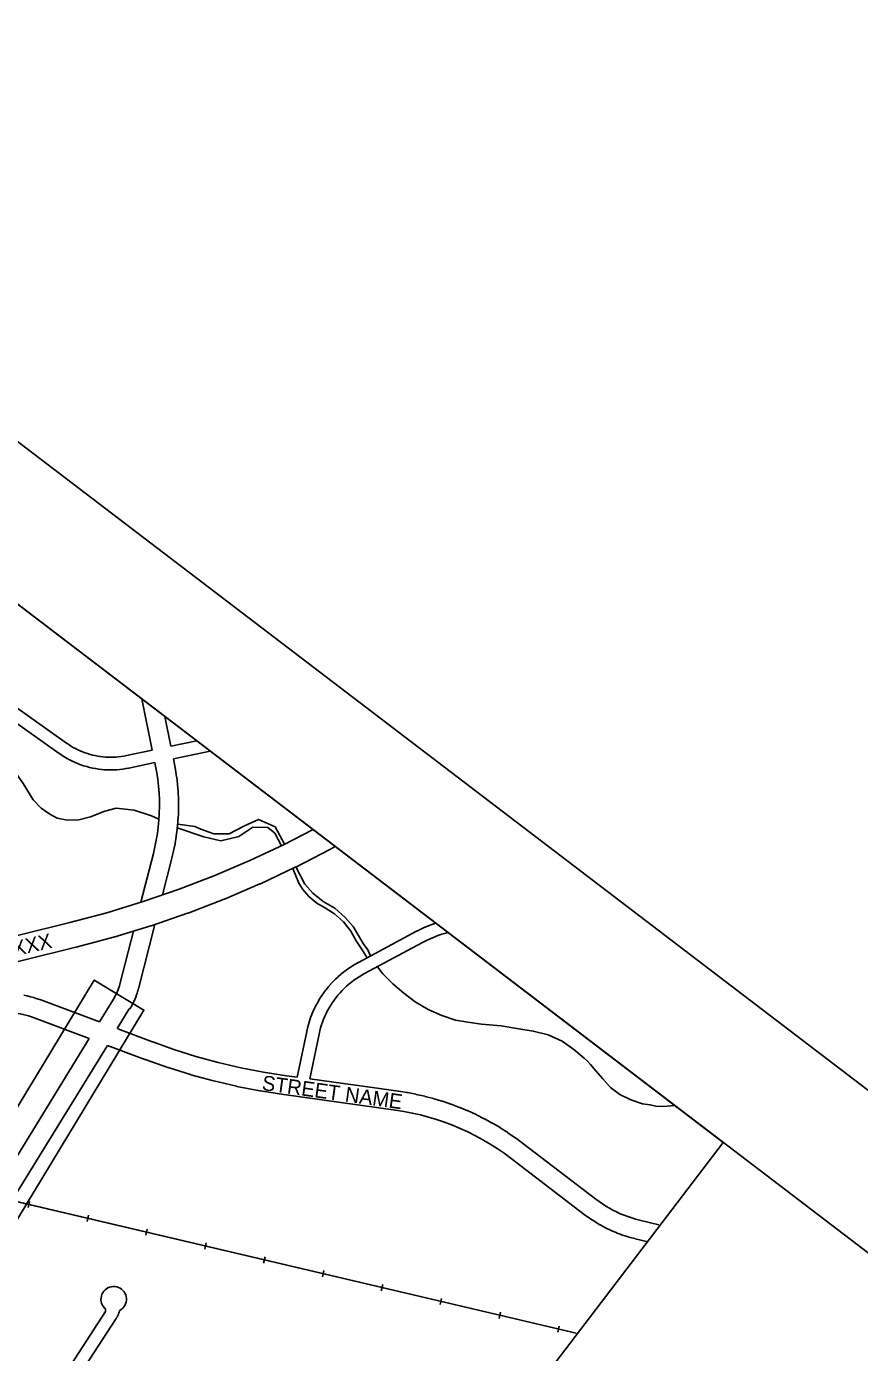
# Model space of a CAD drawing. Extents: x 599744 to 600217, y 4827560 to 4828065.
# Drawn here: x 600025.2 to 600064.4, y 4827997.7 to 4828060.2 of the extents above; entities that cross this region are included whole.
import ezdxf

# ---------------------------------------------------------------- set-up
doc = ezdxf.new("R2010")
doc.units = 0
for name, color, linetype in [('G-ANNO-KEYP', 7, 'Continuous'), ('G-TTLB-OTLN', 7, 'Continuous'), ('G-TTLB-OTLN-PB', 7, 'Continuous')]:
    doc.layers.add(name, color=color, linetype=linetype)

msp = doc.modelspace()

# ---------------------------------------------------------------- linework, layer by layer
at = {"layer": 'G-ANNO-KEYP'}
for p, q in [((600051.473, 4828011.574), (600051.624, 4828011.436)), ((600051.095, 4827998.607), (600022.395, 4828005.359)), ((600025.326, 4828004.824), (600025.257, 4828004.532)), ((600028.1, 4828004.171), (600028.032, 4828003.879)), ((600030.875, 4828003.518), (600030.806, 4828003.226)), ((600033.649, 4828002.866), (600033.58, 4828002.574)), ((600036.423, 4828002.213), (600036.355, 4828001.921)), ((600039.198, 4828001.56), (600039.129, 4828001.268)), ((600041.972, 4828000.908), (600041.903, 4828000.616)), ((600044.746, 4828000.255), (600044.678, 4827999.963)), ((600047.521, 4827999.602), (600047.452, 4827999.31)), ((600050.295, 4827998.95), (600050.226, 4827998.658))]:
    msp.add_line(p, q, dxfattribs=at)
for points in [[(600031.107, 4828026.096), (600029.887, 4828025.842), (600029.764, 4828025.818), (600029.642, 4828025.799), (600029.52, 4828025.784), (600029.397, 4828025.774), (600029.274, 4828025.768), (600029.151, 4828025.766), (600029.027, 4828025.768), (600028.904, 4828025.774), (600028.781, 4828025.784), (600028.659, 4828025.799), (600028.537, 4828025.818), (600028.416, 4828025.841), (600028.297, 4828025.868), (600028.177, 4828025.9), (600028.059, 4828025.935), (600027.942, 4828025.974), (600027.827, 4828026.018), (600027.713, 4828026.065), (600027.601, 4828026.116), (600027.491, 4828026.171), (600027.383, 4828026.23), (600027.276, 4828026.292), (600027.172, 4828026.358), (600027.068, 4828026.429), (600023.676, 4828028.831)], [(600031.107, 4828026.096), (600030.611, 4828028.515)], [(600031.227, 4828025.509), (600030.007, 4828025.255), (600030.002, 4828025.254), (600030.002, 4828025.254), (600029.871, 4828025.229), (600029.861, 4828025.227), (600029.861, 4828025.227), (600029.729, 4828025.207), (600029.72, 4828025.205), (600029.719, 4828025.205), (600029.587, 4828025.189), (600029.587, 4828025.189), (600029.587, 4828025.189), (600029.586, 4828025.189), (600029.586, 4828025.189), (600029.576, 4828025.188), (600029.443, 4828025.177), (600029.442, 4828025.177), (600029.433, 4828025.176), (600029.299, 4828025.169), (600029.298, 4828025.17), (600029.289, 4828025.169), (600029.156, 4828025.167), (600029.154, 4828025.167), (600029.145, 4828025.167), (600029.012, 4828025.169), (600029.01, 4828025.17), (600029.002, 4828025.169), (600028.868, 4828025.176), (600028.866, 4828025.177), (600028.858, 4828025.177), (600028.725, 4828025.188), (600028.723, 4828025.189), (600028.715, 4828025.189), (600028.583, 4828025.205), (600028.579, 4828025.207), (600028.572, 4828025.207), (600028.44, 4828025.227), (600028.437, 4828025.229), (600028.43, 4828025.229), (600028.299, 4828025.254), (600028.295, 4828025.256), (600028.289, 4828025.256), (600028.159, 4828025.285), (600028.155, 4828025.288), (600028.149, 4828025.288), (600028.02, 4828025.322), (600028.015, 4828025.324), (600028.01, 4828025.325), (600027.882, 4828025.363), (600027.877, 4828025.366), (600027.873, 4828025.366), (600027.746, 4828025.409), (600027.741, 4828025.412), (600027.736, 4828025.412), (600027.611, 4828025.459), (600027.606, 4828025.462), (600027.602, 4828025.463), (600027.479, 4828025.514), (600027.472, 4828025.518), (600027.469, 4828025.518), (600027.348, 4828025.573), (600027.341, 4828025.577), (600027.339, 4828025.578), (600027.219, 4828025.637), (600027.212, 4828025.642), (600027.21, 4828025.642), (600027.093, 4828025.706), (600027.086, 4828025.71), (600027.084, 4828025.711), (600026.969, 4828025.778), (600026.961, 4828025.783), (600026.96, 4828025.784), (600026.847, 4828025.855), (600026.839, 4828025.86), (600026.839, 4828025.861), (600026.728, 4828025.936), (600026.724, 4828025.939), (600026.724, 4828025.939), (600023.332, 4828028.341)], [(600031.423, 4828022.843), (600031.069, 4828022.999), (600030.258, 4828023.267), (600029.409, 4828023.358), (600028.876, 4828023.215), (600028.192, 4828022.961), (600027.646, 4828022.814), (600027.113, 4828022.802), (600026.619, 4828022.899), (600026.276, 4828023.086), (600025.874, 4828023.361), (600025.496, 4828023.753), (600025.019, 4828024.527), (600024.778, 4828024.893), (600024.478, 4828025.28), (600024.088, 4828025.705), (600023.545, 4828026.035), (600022.805, 4828026.349), (600021.978, 4828026.699), (600021.327, 4828027.074), (600020.789, 4828027.56), (600020.706, 4828027.738)], [(600031.699, 4828027.685), (600031.987, 4828026.279)], [(600033.209, 4828026.533), (600031.987, 4828026.279)], [(600032.108, 4828025.692), (600033.839, 4828026.053)], [(600030.572, 4828018.933), (600031.16, 4828021.23), (600031.235, 4828021.543), (600031.298, 4828021.856), (600031.35, 4828022.171), (600031.391, 4828022.486), (600031.421, 4828022.804), (600031.44, 4828023.122), (600031.447, 4828023.441), (600031.444, 4828023.76), (600031.43, 4828024.078), (600031.404, 4828024.396), (600031.367, 4828024.713), (600031.32, 4828025.028), (600031.261, 4828025.345), (600031.227, 4828025.509)], [(600032.108, 4828025.692), (600032.142, 4828025.522), (600032.144, 4828025.515), (600032.144, 4828025.515), (600032.205, 4828025.186), (600032.208, 4828025.171), (600032.208, 4828025.17), (600032.258, 4828024.84), (600032.26, 4828024.828), (600032.26, 4828024.824), (600032.298, 4828024.492), (600032.298, 4828024.492), (600032.3, 4828024.476), (600032.327, 4828024.143), (600032.326, 4828024.142), (600032.328, 4828024.127), (600032.343, 4828023.793), (600032.342, 4828023.791), (600032.343, 4828023.777), (600032.347, 4828023.443), (600032.346, 4828023.44), (600032.347, 4828023.427), (600032.339, 4828023.093), (600032.337, 4828023.09), (600032.338, 4828023.077), (600032.318, 4828022.743), (600032.317, 4828022.739), (600032.317, 4828022.727), (600032.285, 4828022.394), (600032.284, 4828022.39), (600032.284, 4828022.379), (600032.241, 4828022.047), (600032.239, 4828022.042), (600032.238, 4828022.032), (600032.184, 4828021.702), (600032.181, 4828021.696), (600032.181, 4828021.686), (600032.115, 4828021.358), (600032.112, 4828021.352), (600032.112, 4828021.343), (600032.034, 4828021.017), (600032.033, 4828021.014), (600032.032, 4828021.01), (600031.587, 4828019.27)], [(600005.072, 4828012.476), (600027.218, 4828017.966), (600028.959, 4828018.431), (600030.677, 4828018.956), (600032.375, 4828019.541), (600034.051, 4828020.187), (600035.703, 4828020.892), (600037.329, 4828021.656), (600038.687, 4828022.354)], [(600037.2, 4828021.595), (600036.879, 4828022.179), (600036.553, 4828022.452), (600035.854, 4828022.471), (600035.186, 4828022.029), (600034.346, 4828021.826), (600033.537, 4828022.011), (600032.289, 4828022.436)], [(600032.306, 4828022.607), (600033.117, 4828022.506), (600033.393, 4828022.372), (600034.008, 4828022.151), (600034.737, 4828022.156), (600035.429, 4828022.516), (600036.11, 4828022.832), (600036.908, 4828022.482), (600037.343, 4828021.663)], [(600039.735, 4828021.554), (600039.503, 4828021.425), (600039.492, 4828021.421), (600039.484, 4828021.415), (600037.868, 4828020.584), (600037.856, 4828020.58), (600037.848, 4828020.575), (600036.203, 4828019.802), (600036.19, 4828019.798), (600036.184, 4828019.793), (600034.512, 4828019.08), (600034.498, 4828019.076), (600034.492, 4828019.072), (600032.796, 4828018.418), (600032.781, 4828018.414), (600032.776, 4828018.411), (600031.058, 4828017.818), (600031.041, 4828017.815), (600031.037, 4828017.812), (600029.299, 4828017.281), (600029.282, 4828017.277), (600029.278, 4828017.275), (600027.522, 4828016.806), (600027.513, 4828016.804), (600027.512, 4828016.804), (600003.91, 4828010.952)], [(600037.727, 4828020.517), (600038.017, 4828019.82), (600038.2, 4828019.528), (600038.491, 4828019.203), (600038.872, 4828018.892), (600039.27, 4828018.653), (600039.695, 4828018.383), (600040.116, 4828018.007), (600040.462, 4828017.569), (600040.725, 4828017.112), (600040.997, 4828016.692), (600041.239, 4828016.312)], [(600041.396, 4828016.396), (600041.267, 4828016.691), (600041.054, 4828016.99), (600040.833, 4828017.368), (600040.578, 4828017.785), (600040.203, 4828018.212), (600039.706, 4828018.655), (600039.163, 4828018.968), (600038.675, 4828019.354), (600038.302, 4828019.788), (600037.881, 4828020.591)], [(600031.228, 4828017.873), (600030.452, 4828014.841), (600030.45, 4828014.838), (600030.45, 4828014.834), (600030.423, 4828014.737), (600030.42, 4828014.73), (600030.419, 4828014.723), (600030.389, 4828014.627), (600030.385, 4828014.619), (600030.385, 4828014.613), (600030.352, 4828014.518), (600030.347, 4828014.51), (600030.346, 4828014.504), (600030.31, 4828014.411), (600030.306, 4828014.402), (600030.305, 4828014.397), (600030.266, 4828014.304), (600030.26, 4828014.295), (600030.26, 4828014.291), (600030.217, 4828014.2), (600030.212, 4828014.19), (600030.211, 4828014.186), (600030.166, 4828014.097), (600030.159, 4828014.087), (600030.159, 4828014.084), (600030.111, 4828013.996), (600030.104, 4828013.985), (600030.103, 4828013.983), (600030.052, 4828013.897), (600030.048, 4828013.891)], [(600044.462, 4828017.948), (600044.375, 4828017.918), (600044.372, 4828017.916), (600044.365, 4828017.914), (600044.17, 4828017.839), (600044.167, 4828017.837), (600044.16, 4828017.835), (600043.968, 4828017.753), (600043.965, 4828017.751), (600043.959, 4828017.749), (600043.77, 4828017.66), (600043.766, 4828017.657), (600043.76, 4828017.655), (600043.574, 4828017.56), (600043.572, 4828017.559), (600043.57, 4828017.558), (600040.825, 4828016.091), (600040.823, 4828016.09)], [(600028.619, 4828013.284), (600029.28, 4828014.358), (600029.325, 4828014.435), (600029.366, 4828014.509), (600029.405, 4828014.585), (600029.441, 4828014.663), (600029.474, 4828014.741), (600029.504, 4828014.82), (600029.532, 4828014.901), (600029.558, 4828014.982), (600029.581, 4828015.068), (600030.22, 4828017.562)], [(600045.046, 4828017.503), (600044.953, 4828017.477), (600044.763, 4828017.419), (600044.576, 4828017.354), (600044.391, 4828017.282), (600044.208, 4828017.204), (600044.029, 4828017.12), (600043.85, 4828017.028), (600041.11, 4828015.564), (600040.979, 4828015.492), (600040.854, 4828015.416)], [(600040.823, 4828016.09), (600040.821, 4828016.089), (600040.683, 4828016.012), (600040.679, 4828016.009), (600040.674, 4828016.007), (600040.539, 4828015.926), (600040.535, 4828015.922), (600040.531, 4828015.92), (600040.399, 4828015.834), (600040.394, 4828015.83), (600040.39, 4828015.828), (600040.262, 4828015.738), (600040.257, 4828015.733), (600040.253, 4828015.732), (600040.128, 4828015.637), (600040.122, 4828015.632), (600040.119, 4828015.63), (600039.997, 4828015.531), (600039.992, 4828015.525), (600039.989, 4828015.524), (600039.871, 4828015.421), (600039.865, 4828015.415), (600039.863, 4828015.414), (600039.748, 4828015.306), (600039.742, 4828015.3), (600039.741, 4828015.299), (600039.63, 4828015.187), (600039.624, 4828015.18), (600039.623, 4828015.18), (600039.516, 4828015.064), (600039.509, 4828015.057), (600039.509, 4828015.057), (600039.406, 4828014.938), (600039.399, 4828014.93), (600039.399, 4828014.93), (600039.3, 4828014.807), (600039.297, 4828014.803), (600039.294, 4828014.799), (600039.2, 4828014.673), (600039.2, 4828014.673), (600039.193, 4828014.664), (600039.104, 4828014.535), (600039.103, 4828014.535), (600039.098, 4828014.527), (600039.012, 4828014.395), (600039.012, 4828014.393), (600039.007, 4828014.386), (600038.926, 4828014.251), (600038.926, 4828014.249), (600038.921, 4828014.241), (600038.845, 4828014.104), (600038.845, 4828014.101)], [(600040.854, 4828015.416), (600040.73, 4828015.335), (600040.611, 4828015.251), (600040.493, 4828015.162), (600040.379, 4828015.07), (600040.269, 4828014.973), (600040.162, 4828014.873), (600040.058, 4828014.769), (600039.958, 4828014.661), (600039.862, 4828014.55), (600039.77, 4828014.435), (600039.682, 4828014.318), (600039.598, 4828014.198), (600039.518, 4828014.074), (600039.443, 4828013.948), (600039.372, 4828013.819), (600039.306, 4828013.689), (600039.244, 4828013.555), (600039.187, 4828013.42), (600039.135, 4828013.282), (600039.088, 4828013.144), (600039.045, 4828013.003), (600039.008, 4828012.861), (600038.975, 4828012.715), (600038.532, 4828010.597)], [(600041.721, 4828015.891), (600041.98, 4828015.561), (600042.44, 4828015.081), (600042.96, 4828014.641), (600043.493, 4828014.226), (600044.109, 4828013.878), (600044.759, 4828013.597), (600045.405, 4828013.373), (600045.98, 4828013.278), (600046.621, 4828013.186), (600047.547, 4828013.102), (600048.287, 4828012.977), (600049.066, 4828012.858), (600049.77, 4828012.671), (600050.422, 4828012.38), (600050.976, 4828011.991), (600051.369, 4828011.664), (600051.473, 4828011.574)], [(600025.05, 4828014.547), (600025.2, 4828014.516), (600025.207, 4828014.513), (600025.215, 4828014.512), (600025.365, 4828014.476), (600025.372, 4828014.473), (600025.38, 4828014.472), (600025.528, 4828014.431), (600025.535, 4828014.427), (600025.542, 4828014.426), (600025.689, 4828014.38), (600025.697, 4828014.375), (600025.703, 4828014.375), (600025.848, 4828014.323), (600025.852, 4828014.321), (600025.856, 4828014.321), (600028.619, 4828013.284)], [(600038.845, 4828014.101), (600038.84, 4828014.094), (600038.769, 4828013.954), (600038.769, 4828013.951), (600038.765, 4828013.945), (600038.699, 4828013.802), (600038.698, 4828013.799), (600038.694, 4828013.792), (600038.633, 4828013.647), (600038.633, 4828013.644), (600038.63, 4828013.638), (600038.574, 4828013.491), (600038.573, 4828013.486), (600038.57, 4828013.481), (600038.519, 4828013.332), (600038.519, 4828013.327), (600038.516, 4828013.322), (600038.471, 4828013.171), (600038.47, 4828013.166), (600038.468, 4828013.161), (600038.428, 4828013.009), (600038.427, 4828013.003), (600038.425, 4828012.999), (600038.39, 4828012.845), (600038.39, 4828012.842), (600038.389, 4828012.84), (600037.937, 4828010.679)], [(600028.141, 4828012.503), (600025.543, 4828013.477), (600025.409, 4828013.525), (600025.278, 4828013.567), (600025.144, 4828013.604), (600025.009, 4828013.637), (600024.875, 4828013.665), (600024.738, 4828013.688), (600024.601, 4828013.707), (600024.463, 4828013.721), (600024.325, 4828013.731), (600024.187, 4828013.736), (600024.048, 4828013.736), (600023.91, 4828013.731), (600023.773, 4828013.722), (600023.635, 4828013.707), (600023.498, 4828013.689), (600023.361, 4828013.665)], [(600030.025, 4828013.906), (600030.025, 4828013.905), (600029.454, 4828012.977)], [(600029.477, 4828012.962), (600031.071, 4828012.364), (600031.071, 4828012.364), (600031.098, 4828012.354), (600031.127, 4828012.344), (600031.127, 4828012.344), (600031.127, 4828012.344), (600032.13, 4828011.989), (600033.169, 4828011.663), (600034.22, 4828011.376), (600035.281, 4828011.128), (600036.35, 4828010.919), (600037.431, 4828010.749), (600037.937, 4828010.679)], [(600023.749, 4828005.364), (600028.14, 4828012.504)], [(600028.997, 4828012.181), (600024.667, 4828005.141)], [(600054.398, 4828002.937), (600053.864, 4828003.067), (600053.861, 4828003.069), (600053.856, 4828003.069), (600053.656, 4828003.122), (600053.649, 4828003.125), (600053.641, 4828003.126), (600053.442, 4828003.185), (600053.434, 4828003.189), (600053.427, 4828003.19), (600053.23, 4828003.256), (600053.222, 4828003.261), (600053.216, 4828003.262), (600053.022, 4828003.335), (600053.013, 4828003.34), (600053.007, 4828003.34), (600052.816, 4828003.42), (600052.806, 4828003.426), (600052.801, 4828003.426), (600052.613, 4828003.513), (600052.603, 4828003.519), (600052.599, 4828003.519), (600052.413, 4828003.612), (600052.403, 4828003.619), (600052.399, 4828003.619), (600052.217, 4828003.718), (600052.206, 4828003.725), (600052.203, 4828003.726), (600052.025, 4828003.831), (600052.013, 4828003.839), (600052.011, 4828003.84), (600051.836, 4828003.951), (600051.825, 4828003.959), (600051.823, 4828003.96), (600051.652, 4828004.077), (600051.64, 4828004.086), (600051.64, 4828004.086), (600051.473, 4828004.209), (600051.467, 4828004.214), (600051.467, 4828004.214), (600048.021, 4828006.854), (600047.699, 4828007.092), (600047.371, 4828007.317), (600047.036, 4828007.531), (600046.694, 4828007.733), (600046.344, 4828007.923), (600045.989, 4828008.101), (600045.628, 4828008.267), (600045.261, 4828008.42), (600044.89, 4828008.561), (600044.513, 4828008.688), (600044.133, 4828008.803), (600043.749, 4828008.904), (600043.361, 4828008.992), (600042.971, 4828009.067), (600042.574, 4828009.129), (600037.303, 4828009.859), (600037.3, 4828009.86), (600037.295, 4828009.86), (600036.202, 4828010.032), (600036.196, 4828010.035), (600036.186, 4828010.035), (600035.1, 4828010.247), (600035.094, 4828010.25), (600035.084, 4828010.25), (600034.007, 4828010.502), (600034, 4828010.506), (600033.991, 4828010.506), (600032.924, 4828010.798), (600032.916, 4828010.802), (600032.908, 4828010.803), (600031.853, 4828011.133), (600031.844, 4828011.138), (600031.837, 4828011.138), (600030.826, 4828011.496), (600030.826, 4828011.496), (600030.794, 4828011.508), (600030.79, 4828011.51), (600030.787, 4828011.511), (600030.755, 4828011.522), (600030.755, 4828011.522), (600028.997, 4828012.182)], [(600051.624, 4828011.436), (600051.757, 4828011.285), (600052.018, 4828010.988), (600052.35, 4828010.602), (600052.703, 4828010.202), (600053.142, 4828009.867), (600053.661, 4828009.608), (600054.223, 4828009.429), (600054.568, 4828009.37), (600054.572, 4828009.376), (600054.844, 4828009.318), (600055.226, 4828009.304), (600055.703, 4828009.348), (600055.732, 4828009.351)], [(600038.532, 4828010.597), (600041.71, 4828010.157), (600041.71, 4828010.157), (600042.701, 4828010.019), (600042.704, 4828010.018), (600042.709, 4828010.018), (600043.117, 4828009.955), (600043.122, 4828009.952), (600043.132, 4828009.952), (600043.538, 4828009.874), (600043.544, 4828009.872), (600043.553, 4828009.871), (600043.955, 4828009.78), (600043.962, 4828009.776), (600043.97, 4828009.776), (600044.37, 4828009.67), (600044.377, 4828009.667), (600044.385, 4828009.666), (600044.78, 4828009.547), (600044.788, 4828009.543), (600044.795, 4828009.543), (600045.186, 4828009.41), (600045.194, 4828009.406), (600045.2, 4828009.405), (600045.587, 4828009.259), (600045.595, 4828009.254), (600045.601, 4828009.253), (600045.982, 4828009.094)], [(600045.982, 4828009.094), (600045.991, 4828009.088), (600045.996, 4828009.088), (600046.371, 4828008.916), (600046.381, 4828008.91), (600046.385, 4828008.909), (600046.755, 4828008.724), (600046.765, 4828008.717), (600046.768, 4828008.717), (600047.131, 4828008.519), (600047.142, 4828008.512), (600047.144, 4828008.512), (600047.5, 4828008.302), (600047.511, 4828008.294), (600047.513, 4828008.294), (600047.861, 4828008.072), (600047.873, 4828008.063), (600047.874, 4828008.063), (600048.214, 4828007.829), (600048.226, 4828007.82), (600048.227, 4828007.82), (600048.559, 4828007.575), (600048.565, 4828007.57), (600048.565, 4828007.57), (600052.011, 4828004.93), (600052.168, 4828004.814), (600052.326, 4828004.705), (600052.488, 4828004.602), (600052.654, 4828004.505), (600052.822, 4828004.413), (600052.994, 4828004.327), (600053.168, 4828004.247), (600053.346, 4828004.174), (600053.525, 4828004.106), (600053.707, 4828004.045), (600053.891, 4828003.99), (600054.081, 4828003.94), (600054.993, 4828003.718)], [(600051.095, 4827998.607), (600022.395, 4828005.359), (600022.332, 4828005.373), (600021.896, 4828005.471), (600021.46, 4828005.561), (600021.022, 4828005.643), (600020.585, 4828005.716), (600020.145, 4828005.782), (600019.704, 4828005.843), (600019.262, 4828005.893), (600018.819, 4828005.936), (600018.374, 4828005.971), (600017.929, 4828006), (600017.485, 4828006.019), (600017.041, 4828006.032), (600016.596, 4828006.037), (600016.15, 4828006.033), (600015.707, 4828006.022), (600015.26, 4828006.004), (600014.818, 4828005.977), (600014.372, 4828005.943), (600013.93, 4828005.9), (600013.487, 4828005.851)], [(600026.008, 4827995.17), (600028.908, 4827999.634), (600028.908, 4827999.753), (600028.847, 4827999.812), (600028.794, 4827999.879), (600028.752, 4827999.952), (600028.72, 4828000.031), (600028.7, 4828000.113), (600028.691, 4828000.197), (600028.695, 4828000.282), (600028.71, 4828000.365), (600028.737, 4828000.446), (600028.775, 4828000.522), (600028.824, 4828000.591), (600028.881, 4828000.653), (600028.947, 4828000.707), (600029.02, 4828000.75), (600029.098, 4828000.783), (600029.18, 4828000.805), (600029.264, 4828000.814), (600029.349, 4828000.812), (600029.433, 4828000.798), (600029.514, 4828000.772), (600029.59, 4828000.735), (600029.66, 4828000.688), (600029.723, 4828000.631), (600029.778, 4828000.566), (600029.822, 4828000.494), (600029.856, 4828000.416), (600029.879, 4828000.335), (600029.89, 4828000.251), (600029.889, 4828000.166), (600029.876, 4828000.082), (600029.851, 4828000.001), (600029.816, 4827999.924), (600029.769, 4827999.853), (600029.714, 4827999.789), (600029.649, 4827999.734), (600029.578, 4827999.688), (600029.548, 4827999.625), (600029.547, 4827999.619), (600029.54, 4827999.593), (600029.538, 4827999.588), (600029.537, 4827999.582), (600029.529, 4827999.556), (600029.526, 4827999.551), (600029.526, 4827999.546), (600029.516, 4827999.52), (600029.513, 4827999.514), (600029.513, 4827999.51), (600029.503, 4827999.484), (600029.499, 4827999.478), (600029.498, 4827999.474), (600029.487, 4827999.449), (600029.483, 4827999.442), (600029.483, 4827999.439), (600029.471, 4827999.414), (600029.467, 4827999.407), (600029.466, 4827999.405), (600029.453, 4827999.38), (600029.448, 4827999.373), (600029.448, 4827999.371), (600029.434, 4827999.347), (600029.429, 4827999.339), (600029.429, 4827999.338), (600029.414, 4827999.314), (600029.412, 4827999.31), (600029.411, 4827999.31), (600026.486, 4827994.807)]]:
    msp.add_lwpolyline(points, dxfattribs=at)
msp.add_lwpolyline([(600010.535, 4827985.796), (600028.374, 4828015.258), (600030.714, 4828013.841), (600012.874, 4827984.379)], close=True, dxfattribs=at)
msp.add_lwpolyline([(600010.535, 4827985.796), (600028.374, 4828015.258), (600030.714, 4828013.841), (600012.874, 4827984.379)], close=True, dxfattribs=at)
at = {"layer": 'G-TTLB-OTLN'}
msp.add_line((599997.478, 4828053.792), (600211.005, 4827890.894), dxfattribs=at)
msp.add_lwpolyline([(599983.747, 4827984.522), (600022.202, 4828034.93), (600058.02, 4828007.605), (600019.565, 4827957.197)], close=True, dxfattribs=at)
at = {"layer": 'G-TTLB-OTLN-PB'}
msp.add_lwpolyline([(599961.599, 4827559.688), (600216.766, 4827894.161), (599999.104, 4828060.213), (599743.938, 4827725.74)], close=True, dxfattribs=at)

# ---------------------------------------------------------------- texts
at = {"layer": 'G-ANNO-KEYP'}
for s, rotation, p in [('HIGHWAY XXX', 12.71687, (600019.987, 4828015.335)), ('STREET NAME', 352.11591, (600036.248, 4828010.08))]:
    msp.add_text(s, height=0.7, rotation=rotation, dxfattribs=at).set_placement(p)

doc.saveas('drawing.dxf')
